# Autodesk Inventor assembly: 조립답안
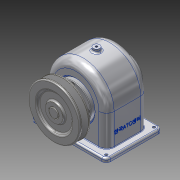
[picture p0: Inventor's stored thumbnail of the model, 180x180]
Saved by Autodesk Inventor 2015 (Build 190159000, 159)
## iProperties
Created: 2016-01
Part Number: 조립답안
Document SubType Name: Assembly
Designer: 601-23
Author: 601-23
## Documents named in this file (16)
- C:\Users\601-23\Desktop\460106V1044\조립답안.iam
- C:\Users\601-23\Desktop\460106V1044\본체.ipt
- C:\Users\601-23\Desktop\460106V1044\축.ipt
- C:\Users\601-23\Desktop\460106V1044\베어링 6203.ipt
- C:\Users\601-23\Desktop\460106V1044\키 - 5 x 5 x 18.ipt
- C:\Users\601-23\Desktop\460106V1044\키 - 6 x 6 x 22.ipt
- C:\Users\601-23\Desktop\460106V1044\부시1.ipt
- C:\Users\601-23\Desktop\460106V1044\스퍼기어.ipt
- C:\Users\601-23\Desktop\460106V1044\앞커버.ipt
- C:\Users\601-23\Desktop\460106V1044\뒤커버.ipt
- C:\Users\601-23\Desktop\460106V1044\부시2.ipt
- C:\Users\601-23\Desktop\460106V1044\오일씰 28 40 8.ipt
- C:\Users\601-23\Desktop\460106V1044\V-벨트풀리.ipt
- C:\Users\601-23\Desktop\460106V1044\멈춤나사 - M4x10.ipt
- C:\Users\601-23\Desktop\460106V1044\볼트 M3 x 8.ipt
- C:\Users\601-23\Desktop\460106V1044\볼트 M3 x 10.ipt
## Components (9 placed, 3 different names)
1. V-벨트풀리:1
2. ISO 4762 M3 x 8:1
3. ISO 4762 M3 x 8:2
4. ISO 4762 M3 x 8:3
5. ISO 4762 M3 x 8:4
6. ISO 4762 M3 x 10:1
7. ISO 4762 M3 x 10:2
8. ISO 4762 M3 x 10:3
9. ISO 4762 M3 x 10:4
